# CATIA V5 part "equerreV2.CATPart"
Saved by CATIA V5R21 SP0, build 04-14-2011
Part number: equerre
Bounding box of the stored display mesh (mm): x -0.995 to 17.005, y -11.441 to 6.559, z -15 to 3
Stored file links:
  C:\Users\2027.DESARCY-LEMIE30\Desktop\V15(20.03.2023)\equerreV2.CATPart
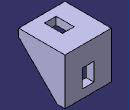
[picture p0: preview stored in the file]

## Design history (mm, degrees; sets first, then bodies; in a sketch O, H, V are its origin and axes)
Body1 (main body)
  Sketch1 on xy-plane, origin (0, 0, 0), H (1, 0, 0), V (0, 1, 0)
    line L1 (-0.9951, 6.5593) -> (17.0049, 6.5593)
    line L2 (17.0049, 6.5593) -> (17.0049, -11.4407)
    line L3 (17.0049, -11.4407) -> (-0.9951, -11.4407)
    line L4 (-0.9951, -11.4407) -> (-0.9951, 6.5593)
    length L2 = 18
    length L1 = 18
    horizontal: L1 H, L3 H
    vertical: L2 V, L4 V
  Pad1: profile Sketch1, direction (0, 0, 1), length 3
  Sketch2 on start face of Pad1, origin (0, 0, 0), H (1, 0, 0), V (0, -1, 0)
    point P1 (17.0049, -3.5593)
    reference projected line E1 (17.0049, 11.4407) -> (17.0049, -6.5593) from edge [start face of Pad1 | face of Pad1 from Sketch1.L2]
    reference projected point E2 (17.0049, -6.5593) from vertex [face of Pad1 from Sketch1.L1 | start face of Pad1 | face of Pad1 from Sketch1.L2]
    line L1 (17.0049, -3.5593) -> (17.0049, -6.5593)
    line L2 (17.0049, -3.5593) -> (-0.9951, -3.5593)
    line L3 (17.0049, -6.5593) -> (-0.9951, -6.5593)
    line L4 (-0.9951, -3.5593) -> (-0.9951, -6.5593)
    distance P1 E2 = 3
    length L2 = 18
    coincidence: P1 E1
    vertical: L1 V, L4 V
    horizontal: L2 H, L3 H
  Pad2: profile Sketch2, direction (0, 0, -1), length 15
  Sketch3 on face of Pad2, origin (17.0049, 0, 0), H (0, 1, 0), V (0, 0, 1)
    point P1 (3.5593, -15)
    point P2 (3.5593, 0)
    point P3 (-11.4407, 0)
    reference projected point E1 (-11.4407, 0) from vertex [face of Pad1 from Sketch1.L2 | start face of Pad1 | face of Pad1 from Sketch1.L3]
    reference projected point E2 (3.5593, 0) from vertex [start face of Pad1 | face of Pad2 | face of Pad2 from Sketch2.L2]
    reference projected point E3 (3.5593, -15) from vertex [face of Pad2 from Sketch2.L1 | end face of Pad2 | face of Pad2 from Sketch2.L2]
    line L1 (-11.4407, 0) -> (3.5593, 0)
    line L2 (3.5593, 0) -> (3.5593, -15)
    line L3 (-11.4407, 0) -> (3.5593, -15)
    coincidence: E1 P3, E2 P2, P1 E3
    horizontal: L1 H
    vertical: L2 V
  Pad3: profile Sketch3, direction (-1, 0, 0), length 3
  Sketch4 on face of Pad2, origin (-0.9951, 0, 0), H (0, -1, 0), V (0, 0, 1)
    point P1 (-3.5593, 0)
    point P2 (11.4407, 0)
    point P3 (-3.5593, -15)
    reference projected point E1 (-3.5593, 0) from vertex [start face of Pad1 | face of Pad2 | face of Pad2 from Sketch2.L2]
    reference projected point E2 (11.4407, 0) from vertex [face of Pad1 from Sketch1.L3 | start face of Pad1 | face of Pad1 from Sketch1.L4]
    reference projected point E3 (-3.5593, -15) from vertex [face of Pad2 from Sketch2.L4 | end face of Pad2 | face of Pad2 from Sketch2.L2]
    line L1 (-3.5593, 0) -> (11.4407, 0)
    line L2 (11.4407, 0) -> (-3.5593, -15)
    line L3 (-3.5593, 0) -> (-3.5593, -15)
    coincidence: E1 P1, E2 P2, E3 P3
    horizontal: L1 H
    vertical: L3 V
  Pad4: profile Sketch4, direction (1, 0, 0), length 3
  Sketch5 on start face of Pad1, origin (0, 0, 0), H (1, 0, 0), V (0, -1, 0)
    point P1 (10.2549, 8.1407)
    point P2 (5.7549, 8.1407)
    point P3 (10.2549, 1.1407)
    reference projected line E1 (-0.9951, -6.5593) -> (17.0049, -6.5593) from edge [face of Pad2 | end face of Pad2]
    reference projected line E2 (17.0049, 11.4407) -> (17.0049, -3.5593) from edge [face of Pad3 from Sketch3.L3 | face of Pad3]
    reference projected line E3 (-0.9951, -3.5593) -> (-0.9951, 11.4407) from edge [face of Pad4 from Sketch4.L2 | face of Pad4]
    line L1 (5.7549, 8.1407) -> (10.2549, 8.1407)
    line L2 (10.2549, 8.1407) -> (10.2549, 1.1407)
    line L3 (10.2549, 1.1407) -> (5.7549, 1.1407)
    line L4 (5.7549, 1.1407) -> (5.7549, 8.1407)
    distance P1 E1 = 14.7
    distance P1 E2 = 6.75
    distance P2 E3 = 6.75
    distance P3 P1 = 7
    horizontal: L1 H, L3 H
    vertical: L2 V, L4 V
  Pocket1: profile Sketch5, direction (0, 0, 1), length 3
  Sketch6 on face of Pad2 from Sketch2.L2, origin (0, 3.5593, 0), H (1, 0, 0), V (0, 0, 1)
    point P1 (5.7549, -4.7)
    point P2 (10.2549, -4.7)
    point P3 (5.7549, -11.7)
    reference projected line E1 (-0.9951, 3) -> (17.0049, 3) from edge [face of Pad1 from Sketch1.L3 | end face of Pad1]
    reference projected line E2 (17.0049, 0) -> (17.0049, -15) from edge [face of Pad3 from Sketch3.L3 | face of Pad3]
    reference projected line E3 (-0.9951, -15) -> (-0.9951, 0) from edge [face of Pad4 from Sketch4.L2 | face of Pad4]
    line L1 (5.7549, -4.7) -> (10.2549, -4.7)
    line L2 (5.7549, -11.7) -> (10.2549, -11.7)
    line L3 (5.7549, -4.7) -> (5.7549, -11.7)
    line L4 (10.2549, -4.7) -> (10.2549, -11.7)
    distance P3 E1 = 14.7
    distance P2 E2 = 6.75
    distance P1 E3 = 6.75
    distance P1 P3 = 7
    horizontal: L1 H, L2 H
    vertical: L3 V, L4 V
  Pocket2: profile Sketch6, direction (0, 1, 0), length 3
